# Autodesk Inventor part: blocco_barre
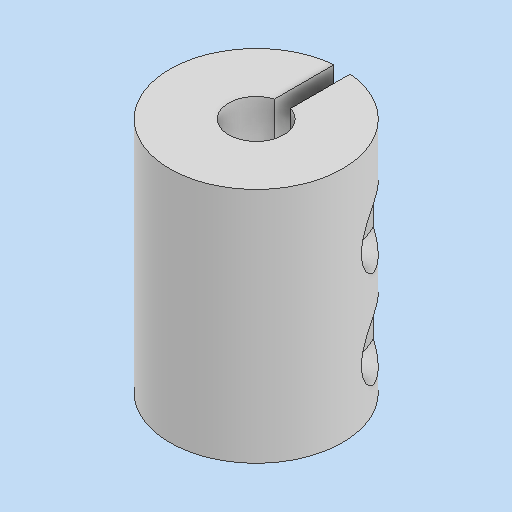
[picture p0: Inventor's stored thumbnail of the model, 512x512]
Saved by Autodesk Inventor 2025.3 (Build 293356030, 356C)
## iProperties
Created: 2025-12
Part Number: blocco_barre
Material: Generico
Document SubType Name: Modeling
Designer: Ryzen5700u
Density: 1 g/cm^3
Appearance: Default
Author: Ryzen5700u
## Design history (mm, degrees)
sketch "Schizzo1"
  geometry: C1 r 8 at (0, 0); 1 further point
  constraints: 1 centre point, 1 coincident
  dimensions: "d0" = 16 diameter of C1
extrude "Estrusione1" new body sketch "Schizzo1" distance "d1" = 22; taper "d2" = 0 deg
sketch "Schizzo2"
  geometry: C1 r 8 at (0, 0) reference; 2 further points
  constraints: 1 coincident
hole "Foro1" sketch "Schizzo2" at (0, 0) diameter "d3" = 5.1; stored, may be unused: countersink angle "d7" = 90 deg, drill point angle "d9" = 118 deg; dims "d4" = 6, "d5" = 10, "d6" = 5.7, "d8" = 11
sketch "Schizzo3"
  geometry: C1 r 8 at (0, 0) reference; 2 further points
  constraints: 1 coincident
hole "Foro2" sketch "Schizzo3" at (0, 0) diameter "d10" = 4.2; stored, may be unused: countersink angle "d14" = 90 deg, drill point angle "d16" = 118 deg; dims "d11" = 6, "d12" = 4, "d13" = 2, "d15" = 11
sketch "Schizzo4"
  geometry: L1 (0.75, 9.587)-(-0.75, 9.587); L2 (-0.75, 9.587)-(-0.75, -9.587); L3 (-0.75, -9.587)-(0.75, -9.587); L4 (0.75, -9.587)-(0.75, 9.587); L5 (0.75, 9.587)-(-0.75, -9.587); L6 (-0.75, 9.587)-(0.75, -9.587); C1 r 2.1 at (0, 0) reference; C2 r 8 at (0, 0) reference; 5 further points
  constraints: 12 end point, 2 midpoint, 2 parallel, 1 horizontal, 1 perpendicular
  dimensions: "d17" = 1.5 distance of L3.end L2.end
extrude "Estrusione2" cut sketch "Schizzo4" extent not by distance; stored distance "d18" = 0; taper "d19" = 0 deg
node "Piano di lavoro1"
node "Piano di lavoro2"
sketch "Schizzo5"
  geometry: L1 (6.003, 0)-(0, 0) reference; 3 further points
  dimensions: "d22" = 9 distance of point (2.931, 14) point (2.931, 5); "d23" = 5 distance from line of L1 point (2.931, 5)
hole "Foro3" sketch "Schizzo5" at (2.931, 5), (2.931, 14) diameter "d24" = 3.2; stored, may be unused: countersink angle "d28" = 90 deg, drill point angle "d30" = 118 deg; dims "d25" = 6, "d26" = 6.5, "d27" = 3.4, "d29" = 8
sketch "Schizzo6"
  geometry: C1 r 1.6 at (2.931, 5) reference; C2 r 1.6 at (2.931, 14) reference; C3 r 3 at (2.931, 5); C4 r 3 at (2.931, 14); 1 further point
  constraints: 2 centre point, 2 coincident
  dimensions: "d33" = 6 diameter of C3; "d34" = 6 diameter of C4
extrude "Estrusione3" cut sketch "Schizzo6" distance "d31" = 10; taper "d32" = 0 deg
mirror "Speculare1"
sketch "Schizzo7"
  geometry: C1 r 3 at (-2.931, 14); A1 r 1.6 centre (-2.931, 5) between (-1.928, 6.247) and (-1.928, 3.753) reference; A2 r 1.6 centre (-2.931, 14) between (-1.928, 15.247) and (-1.928, 12.753) reference; A3 r 3 centre (-2.931, 5) between (-1.928, 7.828) and (-1.928, 2.172) reference; 5 further points
  constraints: 2 coincident, 1 centre point, 2 other
extrude "Estrusione4" cut sketch "Schizzo7" distance "d35" = 1.4; taper "d36" = 0 deg
mirror "Speculare2"
chamfer "Smusso1" distance "d37" = 1; stored, may be unused: second distance "d38" = 2, angle "d39" = 45 deg
node "Solido1"
node "Linea chiusa proiettata1"
other parameters: "d20" = -4.5, "d21" = -5
